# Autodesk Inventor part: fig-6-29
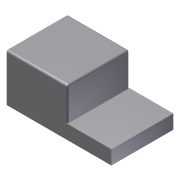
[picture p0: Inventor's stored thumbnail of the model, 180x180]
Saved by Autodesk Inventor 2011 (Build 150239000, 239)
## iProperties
Created: 2004-05
Part Number: fig-6-29
Document SubType Name: Modeling
Designer: CADCIM Technologies
Manufacturer: Standard
Standards Organization: Custom
Density: 1 g/cm^3
Author: CADCIM Technologies
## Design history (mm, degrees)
node "Sketch1"
sketch "Sketch2"
  geometry: L1 (0.098, 47.711)-(0.098, 0.049); L2 (0.098, 0.049)-(-105.483, 0.049); L3 (-105.483, 0.049)-(-105.483, 14.192); L4 (-105.483, 14.192)-(-61.139, 14.192); L5 (-61.139, 14.192)-(-61.139, 47.711); L6 (-61.139, 47.711)-(0.098, 47.711)
  constraints: 12 end point, 3 parallel, 2 perpendicular, 1 vertical
extrude "Extrusion1" new body sketch "Sketch2" stored distance "d0" = 62.5; taper "d1" = 0 deg
fillet "Fillet6" dims "d44" = 2, "d45" = 2, "d46" = 2, "d47" = 2, "d48" = 2, "d49" = 2
body "Solid1"
